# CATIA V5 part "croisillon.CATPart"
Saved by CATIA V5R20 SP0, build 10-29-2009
Part number: croisillon
Bounding box of the stored display mesh (mm): x -5 to 5, y -5 to 5, z -3 to 3
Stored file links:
  C:\Users\Thinkmotion2\Desktop\Pack 2\CFAO_2010\abaussand\CFAO_abaussand_Catia_V5R20\croisillon.CATPart
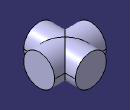
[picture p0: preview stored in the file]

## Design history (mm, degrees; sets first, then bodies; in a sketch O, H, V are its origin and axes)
Body1 (main body)
  Sketch1 on yz-plane, origin (0, 0, 0), H (0, 1, 0), V (0, 0, 1)
    circle A1 centre (0, 0) radius 3
    radius A1 = 3
  Pad1: profile Sketch1, direction (1, 0, 0), length 5, opposite side length 5
  Sketch2 on zx-plane, origin (0, 0, 0), H (-1, 0, 0), V (0, 0, 1)
    circle A1 centre (0, 0) radius 3
    radius A1 = 3
  Pad2: profile Sketch2, direction (0, 1, 0), length 5, opposite side length 5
